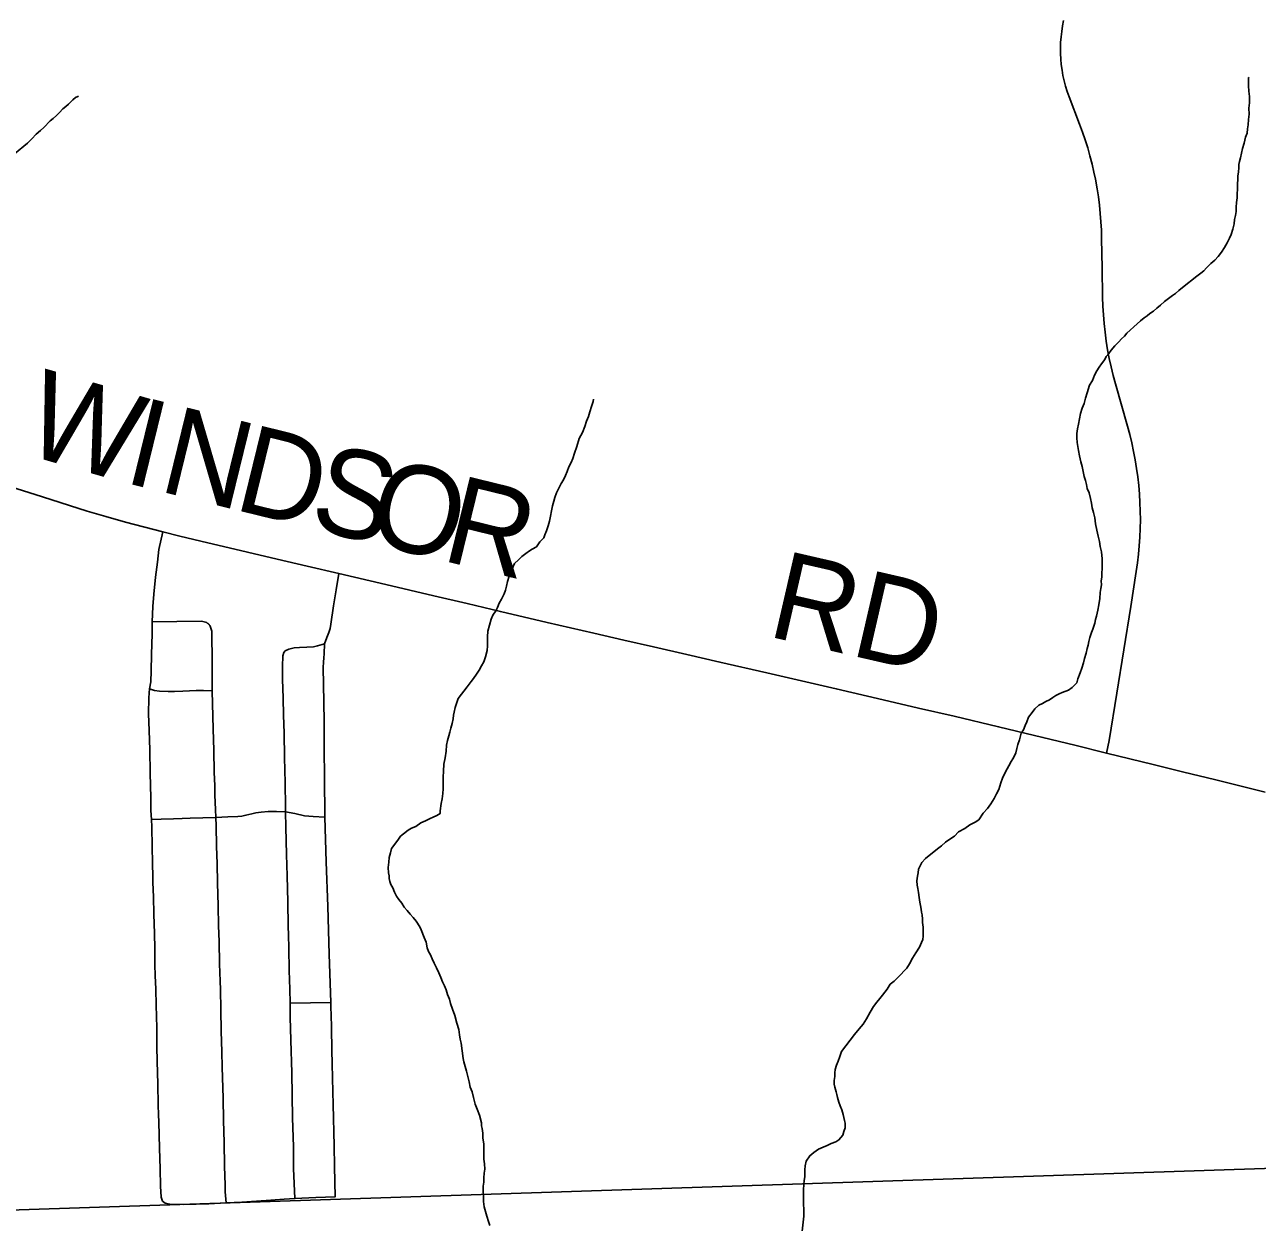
# Model space of a CAD drawing. Extents: x 103424 to 286016, y 38711 to 110967.
# Drawn here: x 153756 to 157992, y 97422 to 101537 of the extents above; entities that cross this region are included whole.
import ezdxf

# ---------------------------------------------------------------- set-up
doc = ezdxf.new("R2010")
doc.units = 0
for name, color, linetype in [('GM_X_Corporation', 7, 'Continuous'), ('GM_X_County_Road', 7, 'Continuous'), ('GM_X_County_Road_Text', 7, 'Continuous'), ('GM_X_Minor_River', 7, 'Continuous'), ('GM_X_Township_Road', 7, 'Continuous')]:
    doc.layers.add(name, color=color, linetype=linetype)

msp = doc.modelspace()

# ---------------------------------------------------------------- linework, layer by layer
at = {"layer": 'GM_X_Corporation'}
msp.add_lwpolyline([(173175.4, 110967.2), (148354.5, 110967.2), (148366.5, 110284), (148366.4, 110242.2), (148494.2, 102114.7), (148500.5, 101714.1), (148505.8, 101377.4), (148509.9, 101119.2), (148594.2, 97294.7), (158050.5, 97608.1), (158064.2, 97608.5), (162306.4, 97749.1), (162479.3, 97753.8), (165116.9, 97825.6), (173478.4, 98058.2), (173457.5, 99090), (173443.3, 99817.2), (173398.5, 101988.3), (173365.2, 103570.9), (173327.2, 105148.6), (173218, 109584.4)], close=True, dxfattribs=at)
msp.add_lwpolyline([(148594.2, 97294.7), (158050.5, 97608.1), (158064.2, 97608.5), (162306.4, 97749.1), (162479.3, 97753.8), (165116.9, 97825.6), (173478.4, 98058.2), (173550.7, 94746.5), (173649.8, 90059.6), (173693.6, 87690.3), (173775.2, 84514.7), (174054.1, 73155.3), (174066.9, 72315.5), (174070.5, 72208.9), (173777.3, 72202), (169136.7, 72130.4), (166950.9, 72068.3), (161596.3, 71930.5), (161287.7, 71923.7), (157064.3, 71829.7), (151578, 71707.7), (149073.5, 71652)], dxfattribs=at)
at = {"layer": 'GM_X_County_Road'}
msp.add_lwpolyline([(153705.5, 99949.7), (153817.9, 99914.4), (153970.9, 99865.5), (154035.2, 99846.7), (154102.2, 99827.2), (154231.4, 99794.8), (154288.8, 99780), (154361.4, 99762.7), (154522, 99724.7), (154624.3, 99700.5), (154726.5, 99676.4), (154836, 99650.7), (154996.8, 99613.4), (155079.4, 99594.2), (155161.9, 99575), (155276.3, 99547.6), (155390.7, 99520.2), (155551.5, 99483.1), (155712.4, 99446), (155814.8, 99422.4), (155917.2, 99398.7), (156031.2, 99372.9), (156145.1, 99347), (156306, 99310), (156425.5, 99282.5), (156545, 99255), (156705.8, 99217.5), (156827.7, 99189), (156949.7, 99160.5), (157102.6, 99124.4), (157255.4, 99088.1), (157364.7, 99061.2), (157473.9, 99034.3), (157634.2, 98994.9), (157739.6, 98969), (157845.1, 98943.2), (157932.1, 98921.7), (158019.1, 98900.2)], dxfattribs=at)
at = {"layer": 'GM_X_Minor_River'}
for points in [[(157543.4, 100476.4), (157555.3, 100486.7), (157567.2, 100499.1), (157579.1, 100509.4), (157591, 100519.7), (157602.9, 100530), (157612.9, 100536.2), (157622.9, 100544.5), (157634.8, 100552.8), (157646.7, 100563.1), (157658.7, 100573.4), (157672.6, 100585.8), (157686.5, 100596.2), (157700.4, 100606.5), (157710.4, 100612.7), (157722.4, 100623.1), (157734.3, 100633.4), (157784, 100672.7), (157798, 100683), (157807.9, 100691.3), (157817.8, 100701.5), (157831.7, 100715.9), (157845.6, 100728.3), (157857.5, 100740.6), (157869.3, 100755), (157879.1, 100771.3), (157888.9, 100787.7), (157896.7, 100803.9), (157902.5, 100816.2), (157908.2, 100834.5), (157912, 100852.7), (157913.7, 100866.9), (157917.5, 100881.1), (157919.2, 100895.3), (157919, 100909.4), (157920.7, 100925.6), (157922.5, 100941.8), (157922.2, 100955.9), (157923.9, 100972.1), (157923.6, 100990.3), (157925.4, 101004.5), (157925.2, 101016.6), (157926.9, 101030.7), (157928.7, 101044.9), (157928.5, 101057), (157930.3, 101067.2), (157934.1, 101079.4), (157937.9, 101095.6), (157941.6, 101111.8), (157947.3, 101130.1), (157951, 101150.4), (157956.8, 101164.6), (157958.6, 101178.8), (157960.3, 101192.9), (157962, 101211.2), (157963.7, 101229.4), (157963.3, 101249.6), (157965, 101267.8), (157964.6, 101290), (157962.3, 101308.1), (157962, 101326.3), (157961.7, 101340.5), (157961.5, 101354.6), (157963.4, 101356.6)], [(153720.6, 101092.8), (153766.3, 101130), (153780.2, 101144.4), (153796.1, 101160.8), (153810, 101173.2), (153821.9, 101183.5), (153843.7, 101206.1), (153853.6, 101214.4), (153865.5, 101224.7), (153875.4, 101235), (153887.3, 101247.3), (153897.3, 101255.5), (153907.2, 101263.8), (153921.1, 101278.2), (153931, 101286.4), (153939, 101290.6), (153941, 101290.7)], [(157138.2, 98990.4), (157146, 99004.7), (157151.9, 99014.9), (157157.8, 99025.1), (157161.6, 99035.3), (157165.4, 99049.5), (157169.2, 99063.7), (157175, 99080), (157180.6, 99102.3), (157188.5, 99114.6), (157194.3, 99128.8), (157200.1, 99141), (157205.9, 99157.3), (157217.7, 99173.7), (157227.5, 99186), (157241.4, 99198.3), (157253.4, 99204.6), (157265.4, 99210.9), (157277.4, 99217.2), (157289.4, 99225.5), (157299.4, 99231.7), (157311.3, 99238), (157321.4, 99242.2), (157343.4, 99250.7), (157355.4, 99259), (157371.2, 99275.4), (157375, 99289.6), (157382.7, 99310), (157388.5, 99326.2), (157394.2, 99344.5), (157398, 99358.7), (157403.7, 99377), (157407.4, 99393.2), (157411.2, 99405.4), (157413, 99417.6), (157416.8, 99431.8), (157422.6, 99448), (157426.4, 99460.2), (157430.3, 99470.4), (157434.1, 99480.6), (157435.9, 99492.7), (157439.7, 99504.9), (157443.4, 99525.2), (157447.1, 99543.4), (157450.8, 99565.7), (157452.4, 99585.9), (157454.2, 99600.1), (157456, 99612.3), (157455.7, 99626.4), (157457.5, 99638.6), (157457.3, 99652.7), (157459, 99668.9), (157458.7, 99685), (157458.4, 99701.2), (157456, 99725.4), (157451.6, 99743.5), (157449.3, 99761.6), (157444.9, 99779.7), (157440.5, 99799.9), (157436.1, 99822), (157433.7, 99842.2), (157429.3, 99860.3), (157425, 99876.3), (157422.7, 99892.5), (157418.4, 99908.6), (157414, 99928.7), (157407.7, 99942.7), (157405.4, 99956.8), (157401.1, 99970.9), (157396.8, 99984.9), (157390.1, 100019.2), (157385.8, 100035.2), (157381.4, 100055.4), (157377.1, 100073.5), (157374.8, 100087.6), (157372.5, 100101.7), (157372.2, 100117.8), (157372, 100132), (157373.7, 100148.1), (157377.4, 100164.4), (157381.2, 100182.6), (157384.9, 100200.9), (157390.6, 100219.2), (157396.4, 100235.4), (157402.1, 100253.7), (157407.8, 100272), (157415.4, 100298.4), (157425.2, 100314.7), (157432.9, 100333), (157440.8, 100347.3), (157448.6, 100359.6), (157456.5, 100371.8), (157468.3, 100386.2), (157472.2, 100396.4), (157482.1, 100406.6), (157489.9, 100418.9), (157501.8, 100433.2), (157515.6, 100447.6), (157525.5, 100457.9), (157535.5, 100466.2), (157543.4, 100476.4)], [(155016.5, 98706), (155038.2, 98734.6), (155048, 98749), (155058, 98757.2), (155073.9, 98769.6), (155085.9, 98775.9), (155099.9, 98782.2), (155117.8, 98794.7), (155133.9, 98801), (155149.9, 98809.4), (155159.9, 98813.6), (155171.9, 98819.9), (155183.9, 98826.1), (155183.7, 98836.2), (155187.3, 98860.5), (155191, 98876.8), (155192.7, 98895), (155194.4, 98911.2), (155194.1, 98931.4), (155193.7, 98951.6), (155195.4, 98971.8), (155196.9, 98996.1), (155200.6, 99018.4), (155204.2, 99040.6), (155205.9, 99060.9), (155209.6, 99077.1), (155213.4, 99093.3), (155217.2, 99105.5), (155221, 99119.7), (155224.7, 99136), (155228.5, 99152.2), (155230.2, 99164.3), (155232.1, 99174.5), (155235.8, 99190.7), (155239.6, 99204.9), (155245.4, 99221.2), (155276.9, 99262.1), (155290.7, 99280.6), (155298.6, 99290.8), (155308.4, 99305.1), (155318.3, 99319.4), (155326.1, 99333.7), (155333.9, 99348), (155339.7, 99364.3), (155345.3, 99386.6), (155347, 99402.8), (155346.8, 99416.9), (155346.5, 99433.1), (155348.2, 99453.3), (155353.8, 99473.6), (155359.5, 99493.9), (155365.3, 99508.2), (155375.2, 99522.5), (155381, 99534.7), (155386.8, 99548.9), (155394.6, 99563.2), (155404.4, 99581.6), (155408.2, 99593.8), (155412, 99608), (155415.7, 99624.2), (155421.4, 99642.5), (155427.2, 99656.7), (155431.1, 99666.9), (155438.8, 99685.2), (155452.7, 99697.6), (155464.6, 99709.9), (155478.6, 99720.3), (155490.5, 99728.6), (155500.5, 99734.8), (155514.5, 99743.1), (155526.3, 99759.5), (155540.1, 99773.9), (155544, 99784.1), (155549.8, 99798.3), (155555.6, 99814.6), (155559.3, 99830.8), (155570.5, 99883.5), (155574.2, 99899.8), (155578, 99911.9), (155583.8, 99928.2), (155591.6, 99944.5), (155599.3, 99960.8), (155607.2, 99973.1), (155615, 99987.4), (155620.8, 100001.6), (155626.6, 100017.9), (155634.4, 100032.1), (155640.2, 100046.4), (155645.9, 100064.7), (155653.6, 100087), (155661.1, 100115.5), (155672.9, 100135.9), (155680.6, 100156.2), (155686.3, 100174.5), (155694.1, 100190.8), (155697.8, 100207), (155703.6, 100225.3), (155709.3, 100241.6), (155711.2, 100249.7)], [(156433.6, 97551.6), (156435.3, 97565.8), (156437.1, 97577.9), (156437, 97588), (156436.7, 97602.1), (156438.5, 97616.3), (156442.2, 97632.5), (156454, 97650.9), (156467.9, 97661.3), (156483.9, 97673.7), (156499.9, 97680), (156513.9, 97686.3), (156527.9, 97692.7), (156543.9, 97699), (156553.9, 97705.2), (156567.7, 97721.7), (156571.6, 97733.8), (156575.4, 97746), (156575.1, 97762.2), (156572.9, 97772.3), (156570.7, 97782.3), (156568.5, 97792.4), (156564.2, 97808.5), (156557.9, 97822.5), (156553.6, 97834.5), (156549.3, 97850.6), (156547.1, 97860.7), (156544.9, 97870.7), (156540.6, 97886.8), (156538.4, 97896.9), (156538.2, 97909), (156539.9, 97923.2), (156539.7, 97935.3), (156541.5, 97947.4), (156545.3, 97961.7), (156551.1, 97975.9), (156556.8, 97992.2), (156562.6, 98008.4), (156607.9, 98067.8), (156623.8, 98086.3), (156637.6, 98102.7), (156649.4, 98121.1), (156661.1, 98143.5), (156672.8, 98163.9), (156684.7, 98178.3), (156694.5, 98190.6), (156704.4, 98202.9), (156712.3, 98213.1), (156720.2, 98223.4), (156730, 98239.7), (156743.9, 98250.1), (156755.8, 98262.4), (156767.7, 98274.7), (156777.6, 98285), (156787.5, 98295.3), (156797.3, 98309.6), (156807, 98330), (156818.8, 98348.4), (156830.6, 98366.8), (156838.4, 98383), (156842.2, 98393.2), (156844, 98405.4), (156843.8, 98419.5), (156843.5, 98435.7), (156841.2, 98451.8), (156841, 98463.9), (156840.7, 98478), (156838.5, 98488.1), (156836.3, 98498.2), (156834.1, 98510.2), (156831.8, 98522.3), (156829.5, 98538.5), (156827.2, 98554.6), (156825, 98568.7), (156822.7, 98580.8), (156822.5, 98594.9), (156824.2, 98611.1), (156826, 98623.2), (156827.8, 98635.4), (156839.5, 98657.8), (156851.3, 98672.2), (156893.1, 98705.2), (156907.1, 98715.6), (156921, 98728), (156934.9, 98738.3), (156950.9, 98748.7), (156964.7, 98763.1), (156986.7, 98775.6), (157004.6, 98788), (157022.6, 98796.5), (157034.6, 98804.7), (157050.3, 98827.3), (157064.2, 98843.7), (157076, 98860), (157087.8, 98878.4), (157095.5, 98894.7), (157103.4, 98909), (157111, 98931.4), (157116.8, 98947.6), (157126.5, 98970), (157138.2, 98990.4)], [(155354.6, 97411), (155350.3, 97425.1), (155343.9, 97443.2), (155339.6, 97459.2), (155335.2, 97475.3), (155332.9, 97493.5), (155332.6, 97511.6), (155332.2, 97529.8), (155332, 97546), (155333.7, 97560.2), (155333.5, 97574.3), (155335.2, 97590.5), (155336.9, 97604.7), (155336.6, 97622.8), (155334.3, 97639), (155334, 97655.1), (155333.7, 97673.3), (155333.4, 97691.5), (155331, 97711.6), (155330.7, 97727.8), (155328.4, 97743.9), (155326.2, 97754), (155326, 97764), (155319.5, 97790.2), (155311.1, 97810.2), (155304.7, 97828.3), (155298.2, 97850.4), (155293.8, 97870.5), (155287.5, 97886.6), (155283.1, 97904.7), (155278.8, 97922.8), (155274.4, 97940.9), (155265.8, 97973.1), (155263.5, 97985.2), (155256.5, 98037.6), (155252.2, 98051.6), (155250, 98065.7), (155247.6, 98083.9), (155241.2, 98106), (155234.7, 98132.1), (155226.2, 98154.2), (155219.8, 98174.3), (155215.5, 98188.3), (155209.1, 98204.4), (155204.8, 98220.5), (155198.5, 98234.5), (155192.2, 98248.5), (155185.9, 98262.6), (155179.6, 98278.6), (155171.2, 98296.6), (155162.8, 98312.6), (155156.5, 98326.7), (155150.2, 98340.7), (155143.9, 98352.7), (155139.7, 98364.8), (155135.3, 98384.9), (155128.9, 98400.9), (155118.4, 98427), (155114.2, 98437), (155101.7, 98457), (155091.4, 98468.9), (155081.1, 98480.9), (155070.8, 98492.8), (155060.5, 98504.7), (155052.2, 98518.7), (155041.9, 98530.7), (155033.6, 98542.6), (155027.3, 98556.7), (155021, 98570.7), (155014.7, 98582.7), (155010.5, 98592.7), (155008.3, 98602.8), (155008.1, 98612.9), (155005.9, 98623), (155005.6, 98641.1), (155007.3, 98659.4), (155009, 98675.5), (155012.7, 98691.8), (155016.5, 98706)], [(156428.4, 97391.9), (156433.5, 97442.5), (156433.1, 97464.7), (156432.8, 97484.9), (156432.4, 97505.1), (156432.1, 97521.2), (156431.9, 97533.4), (156433.6, 97551.6)]]:
    msp.add_lwpolyline(points, dxfattribs=at)
at = {"layer": 'GM_X_Township_Road'}
msp.add_line((154668.4, 98175.2), (154808.1, 98177.7), dxfattribs=at)
for points in [[(157473.9, 99034.3), (157482.5, 99076.9), (157508.9, 99239.9), (157532.9, 99388.6), (157557, 99537.3), (157575.5, 99658.4), (157579.7, 99687.8), (157583.5, 99717.2), (157586.3, 99746.6), (157588.4, 99776.2), (157589.6, 99805.8), (157590.1, 99835.4), (157588.7, 99894.6), (157586.9, 99924.1), (157584.4, 99953.7), (157581.2, 99983.1), (157577.2, 100012.4), (157572.4, 100041.7), (157566.9, 100070.7), (157560.6, 100099.7), (157553.6, 100128.4), (157545.8, 100157), (157504.3, 100302.3), (157496.5, 100331.4), (157489.5, 100360.8), (157482.9, 100390.3), (157477.4, 100420), (157472.6, 100449.8), (157468.7, 100479.8), (157465.4, 100509.8), (157462.9, 100539.9), (157461.2, 100570.1), (157460.4, 100600.2), (157458.7, 100701), (157457, 100801.6), (157456.2, 100830.4), (157454.8, 100859.1), (157452.5, 100887.8), (157449.5, 100916.4), (157445.7, 100944.9), (157441.5, 100973.4), (157435.4, 101006.1), (157430.7, 101029.8), (157424.2, 101057.9), (157416.9, 101085.7), (157409.1, 101113.4), (157400.5, 101140.9), (157391.2, 101168.1), (157381.2, 101195.1), (157345.2, 101289.2), (157338.9, 101307), (157333.2, 101325.2), (157328.4, 101343.6), (157324.1, 101362.2), (157320.9, 101380.9), (157318.3, 101399.8), (157316.6, 101418.7), (157315.6, 101437.6), (157316.1, 101475.7), (157317.7, 101494.7), (157319.7, 101513.5), (157322.7, 101532.4), (157326.5, 101551)], [(154448.3, 97489), (154388.9, 97485.5), (154303.3, 97483.7), (154255, 97484.7), (154238.9, 97487.7), (154230, 97495), (154224.8, 97508.6), (154222.8, 97546.3), (154221.5, 97606.1), (154219.6, 97676.3), (154217.3, 97765.6), (154216.3, 97792.6), (154215.1, 97824.6), (154213.4, 97898.3), (154211.2, 97974.6), (154210.4, 98026.4), (154209.7, 98089.6), (154207.5, 98168.1), (154206.5, 98223.5), (154205, 98269.9), (154203.8, 98306.3), (154203.3, 98363.3), (154201.8, 98414.7), (154199.6, 98480.2), (154198.6, 98540.2), (154196.6, 98589.4), (154196.1, 98607.8), (154195.2, 98656.5), (154194.7, 98711.6), (154192.7, 98780.9), (154191.5, 98806.1), (154190.2, 98836.4), (154189.5, 98880.4), (154189, 98922.6), (154187.5, 98965.1), (154185.8, 99045.2), (154183.6, 99111.4), (154181.8, 99168.7), (154182.4, 99224.1), (154183.4, 99240.3), (154185.1, 99254.6), (154189.7, 99278.5), (154191, 99317.2), (154191.7, 99372.9), (154193.8, 99444.1), (154194.6, 99485), (154196.6, 99537.9), (154200.2, 99580), (154206.2, 99639.1), (154212.3, 99689.8), (154217.1, 99733.3), (154231.4, 99794.8)], [(154448.3, 97489), (154502.9, 97491.7), (154586, 97496.4), (154648.4, 97501), (154684.9, 97503.7), (154679.9, 97606.3), (154679.5, 97681.1), (154677, 97780.6), (154673.8, 97935), (154671.1, 98048.2), (154668.9, 98127.2), (154668.4, 98175.2), (154667.7, 98223.3), (154665.5, 98286.8), (154664.2, 98364.5), (154663, 98408.5), (154662, 98439.1), (154661, 98522.9), (154658.1, 98612.6), (154655.6, 98686.1), (154653.9, 98779.3), (154652.6, 98832.3), (154652.1, 98849.5), (154651.2, 98931.4), (154648.5, 99019.4), (154647.8, 99102.3), (154646, 99164.5), (154644.8, 99223.3), (154642.6, 99288.6), (154642.1, 99331.7), (154643, 99368.6), (154647, 99380.3), (154651.4, 99385.2), (154663.8, 99391.6), (154682.4, 99395.5), (154700.2, 99396.8), (154725.9, 99397.8), (154748.3, 99399.2), (154762.4, 99402.7), (154785.9, 99409.1), (154793.9, 99431.4), (154801.7, 99448.3), (154806, 99461.9), (154808.6, 99476.8), (154817.9, 99539.6), (154826.8, 99595), (154836, 99650.7)], [(154194.6, 99485), (154279.3, 99486), (154364, 99487), (154381.6, 99482.3), (154382.6, 99481.6), (154383.6, 99481), (154384.1, 99480.6), (154385.1, 99479.9), (154385.6, 99479.5), (154386.1, 99479.2), (154386.7, 99478.8), (154387.4, 99478.1), (154387.9, 99477.6), (154388.4, 99477.2), (154389.2, 99476.3), (154389.7, 99475.9), (154390.4, 99475), (154391.2, 99474.1), (154391.9, 99473.2), (154392.7, 99472.2), (154394, 99470.2), (154398.7, 99453.1), (154399.9, 99342.3)], [(154684.9, 97503.7), (154756.5, 97506.8), (154823.1, 97509.7), (154820.7, 97613.7), (154820, 97684.4), (154816.3, 97826.7), (154814.8, 97869.9), (154813.5, 97918), (154812.6, 97966.5), (154812.1, 98013), (154810.6, 98089.6), (154809.1, 98136.3), (154808.6, 98158.5), (154808.1, 98177.7), (154802.8, 98342.7), (154797.5, 98507.6), (154792.6, 98661), (154787.6, 98814.4), (154786.4, 98952.7), (154785.7, 99046.2), (154785, 99139.9), (154784.5, 99210.5), (154782.3, 99328.3), (154783, 99346), (154784.1, 99360.9), (154785.3, 99374.8), (154785.9, 99409.1)], [(154448.3, 97489), (154445.3, 97527.2), (154444.6, 97549.9), (154443.3, 97615.3), (154441.4, 97695.7), (154439.6, 97771.6), (154438.2, 97848), (154435.2, 97954.9), (154433.5, 98007.3), (154431.5, 98079.1), (154429.8, 98152.9), (154428.8, 98221.3), (154427.8, 98251), (154425.8, 98310.5), (154424.3, 98387.3), (154422.6, 98441), (154420.6, 98508.9), (154418.4, 98588.2), (154417.2, 98654.1), (154415, 98713.8), (154414, 98783.8), (154412.7, 98812.5), (154411.7, 98840.8), (154410, 98890), (154409, 98922.4), (154407.8, 98967.5), (154406.3, 99044.7), (154403.8, 99115.8), (154400.6, 99247.8), (154399.9, 99342.3)], [(154185.1, 99254.6), (154202.5, 99249.2), (154219.4, 99246.5), (154249.6, 99245.4), (154270.7, 99246.2)], [(154270.7, 99246.2), (154299.9, 99247.3), (154345.2, 99249.4), (154370.7, 99248.7), (154400.6, 99247.8)], [(154191.5, 98806.1), (154224.9, 98806.8), (154268, 98808.3), (154297.7, 98809.3), (154324.4, 98810.3), (154368.4, 98811.4), (154412.7, 98812.5), (154454, 98815.1), (154489, 98816.4), (154502.6, 98817.7), (154516.2, 98820.3), (154537.1, 98825.7), (154550.9, 98828.3), (154568.8, 98831.5), (154593.1, 98833.2), (154621.1, 98833.9), (154652.6, 98832.3), (154684.2, 98826.1), (154717.4, 98818.9), (154748, 98815.7), (154787.6, 98814.4)]]:
    msp.add_lwpolyline(points, dxfattribs=at)

# ---------------------------------------------------------------- texts
at = {"layer": 'GM_X_County_Road_Text'}
for s, height, rotation, p in [('W', 301.9, 343.9113, (153740.9, 100065.8)), ('I', 301.9, 346.2276, (154089.8, 99965.5)), ('N', 301.9, 346.236, (154210.3, 99935.9)), ('D', 301.9, 346.236, (154468.3, 99872.7)), ('S', 301.9, 346.2347, (154726.3, 99809.5)), ('O', 301.9, 346.2332, (154924.1, 99761.1)), ('R', 301.9, 346.234, (155182.2, 99697.9)), ('RD', 301.87, 347.0423, (156302, 99437.2))]:
    msp.add_text(s, height=height, rotation=rotation, dxfattribs=at).set_placement(p)

doc.saveas('drawing.dxf')
